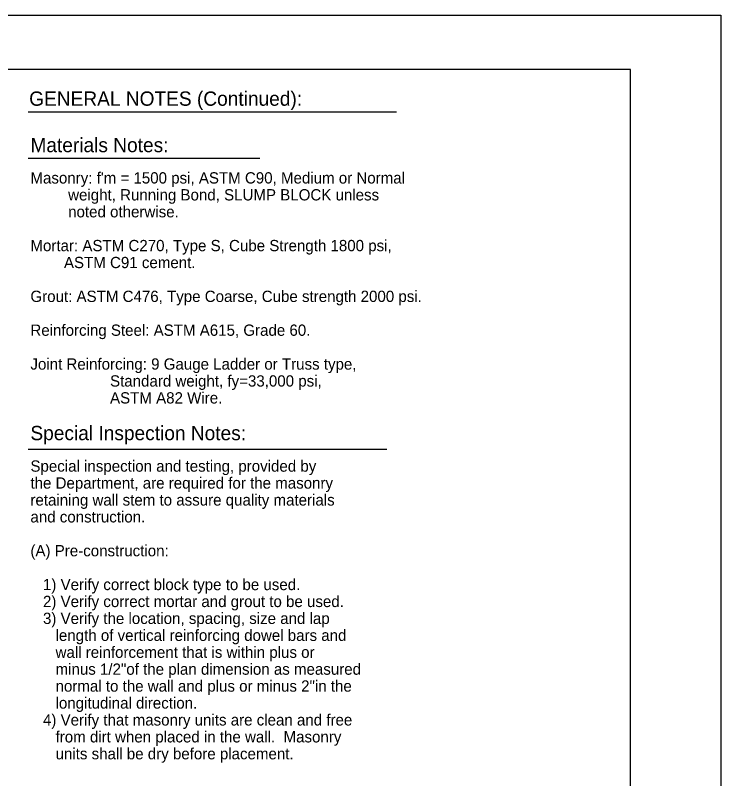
# Model space of a CAD drawing. Extents: x 0 to 2.83, y -0.03 to 1.83.
# Drawn here: x 2.019 to 2.833, y 0.952 to 1.833 of the extents above; entities that cross this region are included whole.
import ezdxf

# ---------------------------------------------------------------- set-up
doc = ezdxf.new("R2010")
doc.units = 0
doc.layers.add('57', color=7, linetype='Continuous')
doc.layers.add('63', color=7, linetype='Continuous')

msp = doc.modelspace()

# ---------------------------------------------------------------- linework, layer by layer
at = {"layer": '57'}
for p, q in [((2.03383, 1.72204), (2.45887, 1.72204)), ((2.03383, 1.66846), (2.30125, 1.66846)), ((2.03383, 1.33258), (2.448, 1.33258))]:
    msp.add_line(p, q, dxfattribs=at)
at = {"layer": '63'}
for p, q in [((0, 1.83333), (2.83333, 1.83333)), ((2.83333, 1.83333), (2.83333, 0))]:
    msp.add_line(p, q, dxfattribs=at)
msp.add_lwpolyline([(2.72918, 1.77077), (0.10418, 1.77077), (0.10418, 0.06244), (2.72918, 0.06244)], close=True, dxfattribs=at)

# ---------------------------------------------------------------- texts
at = {"layer": '57'}
for s, height, p in [('GENERAL NOTES (Continued):', 0.0165, (2.03486, 1.72888)), ('Materials Notes:', 0.0165, (2.03631, 1.6753)), ("Masonry: f'm = 1500 psi, ASTM C90, Medium or Normal", 0.0130208, (2.03631, 1.63912)), ('         weight, Running Bond, SLUMP BLOCK unless', 0.0130208, (2.03631, 1.61959)), ('         noted otherwise.', 0.0130208, (2.03631, 1.60006)), ('Mortar: ASTM C270, Type S, Cube Strength 1800 psi,', 0.0130208, (2.03631, 1.56099)), ('        ASTM C91 cement.', 0.0130208, (2.03631, 1.54146)), ('Grout: ASTM C476, Type Coarse, Cube strength 2000 psi.', 0.0130208, (2.03631, 1.5024)), ('Reinforcing Steel: ASTM A615, Grade 60.', 0.0130208, (2.03631, 1.46334)), ('Joint Reinforcing: 9 Gauge Ladder or Truss type,', 0.0130208, (2.03631, 1.42428)), ('                   Standard weight, fy=33,000 psi,', 0.0130208, (2.03631, 1.40474)), ('                   ASTM A82 Wire.', 0.0130208, (2.03631, 1.38521)), ('Special Inspection Notes:', 0.0165, (2.03631, 1.34287)), ('Special inspection and testing, provided by ', 0.0130208, (2.03631, 1.30649)), ('the Department, are required for the masonry', 0.0130208, (2.03631, 1.28696)), ('retaining wall stem to assure quality materials', 0.0130208, (2.03631, 1.26742)), ('and construction.', 0.0130208, (2.03631, 1.24789)), ('(A) Pre-construction:', 0.0130208, (2.03631, 1.20883)), ('   1) Verify correct block type to be used.', 0.0130208, (2.03631, 1.16977)), ('   2) Verify correct mortar and grout to be used.', 0.0130208, (2.03631, 1.15024)), ('   3) Verify the location, spacing, size and lap', 0.0130208, (2.03631, 1.13071)), ('      length of vertical reinforcing dowel bars and', 0.0130208, (2.03631, 1.11117)), ('      wall reinforcement that is within plus or', 0.0130208, (2.03631, 1.09164)), ('      minus 1/2"of the plan dimension as measured', 0.0130208, (2.03631, 1.07211)), ('      normal to the wall and plus or minus 2"in the', 0.0130208, (2.03631, 1.05258)), ('      longitudinal direction.', 0.0130208, (2.03631, 1.03305)), ('   4) Verify that masonry units are clean and free', 0.0130208, (2.03631, 1.01352)), ('      from dirt when placed in the wall.  Masonry', 0.0130208, (2.03631, 0.99399)), ('      units shall be dry before placement.', 0.0130208, (2.03631, 0.97446))]:
    msp.add_text(s, height=height, dxfattribs=at).set_placement(p)

doc.saveas('drawing.dxf')
